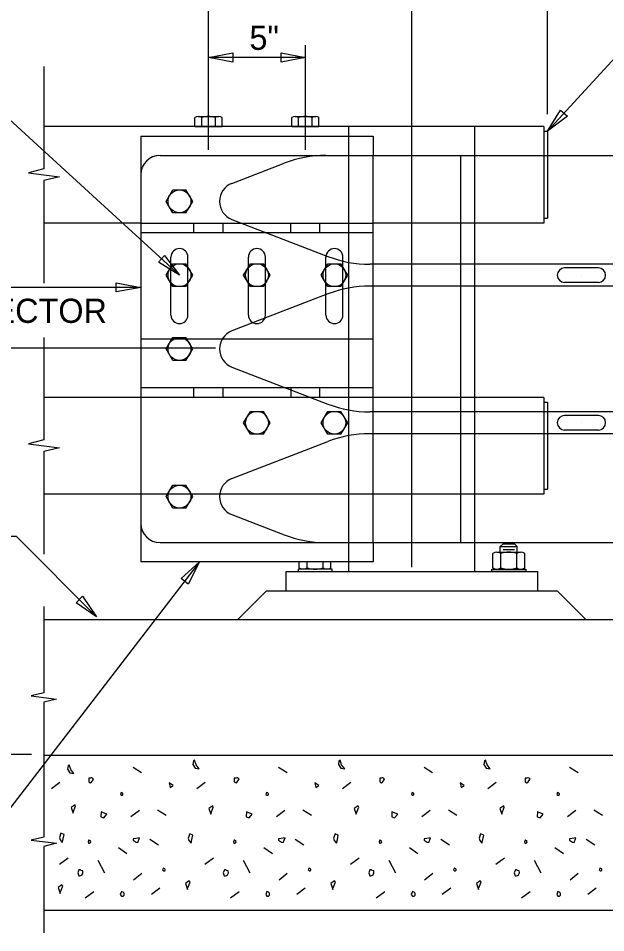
# Model space of a CAD drawing. Extents: x 0 to 22.7, y 0 to 15.7.
# Drawn here: x 17.22 to 19.747, y 9.623 to 13.56 of the extents above; entities that cross this region are included whole.
import ezdxf

# ---------------------------------------------------------------- set-up
doc = ezdxf.new("R2010")
doc.units = 0
for name, color, linetype in [('BRDG_ANNO_General-Notes', 7, 'Continuous'), ('BRDG_BASE_Active-Point', 7, 'Continuous'), ('BRDG_BASE_Dtlctrln', 7, 'Continuous'), ('BRDG_BASE_Hidden-Line', 7, 'Continuous'), ('BRDG_BASE_Obj-Line', 7, 'Continuous'), ('BRDG_BASE_Pattern', 7, 'Continuous'), ('BRDG_BASE_Rebar', 7, 'Continuous'), ('Default', 7, 'Continuous')]:
    doc.layers.add(name, color=color, linetype=linetype)

# ---------------------------------------------------------------- blocks, each defined once
blk = doc.blocks.new('TERM')
at = {"layer": 'Default'}
for p, q in [((-1.6, -0.267), (-1.6, 0.267)), ((-1.6, 0.267), (0, 0)), ((0, 0), (-1.6, -0.267))]:
    blk.add_line(p, q, dxfattribs=at)

msp = doc.modelspace()

# ---------------------------------------------------------------- linework, layer by layer
at = {"layer": 'BRDG_ANNO_General-Notes'}
for p, q in [((19.4969, 13.1468), (19.4969, 13.7448)), ((19.4967, 13.0735), (19.8494, 13.459)), ((18.4552, 13.3912), (18.0385, 13.3912)), ((17.9134, 12.4537), (17.0883, 13.2089)), ((17.7467, 12.4012), (15.937, 12.4012)), ((17.9997, 11.2193), (17.107, 10.0594)), ((17.2776, 10.3896), (15.6191, 10.3896))]:
    msp.add_line(p, q, dxfattribs=at)
msp.add_lwpolyline([(17.5565, 10.9831), (17.212, 11.3293), (16.0973, 11.3293)], dxfattribs=at)
at = {"layer": 'BRDG_BASE_Active-Point'}
for p, q in [((19.6426, 12.4537), (19.6426, 12.4537)), ((19.6426, 11.8183), (19.6426, 11.8183))]:
    msp.add_line(p, q, dxfattribs=at)
at = {"layer": 'BRDG_BASE_Dtlctrln'}
for p, q in [((18.9135, 11.1964), (18.9135, 14.0622)), ((18.0385, 12.9927), (18.0385, 13.7448)), ((18.4552, 12.9927), (18.4552, 13.4437)), ((18.0683, 12.1396), (15.6191, 12.1396))]:
    msp.add_line(p, q, dxfattribs=at)
at = {"layer": 'BRDG_BASE_Hidden-Line'}
for p, q in [((18.6426, 11.2193), (18.6426, 13.0943)), ((19.1842, 11.3027), (19.1842, 13.0943)), ((18.7467, 11.3027), (18.7467, 12.9693)), ((19.4811, 12.9693), (19.4811, 12.6777)), ((19.4967, 12.9693), (19.4967, 12.6985)), ((17.7467, 12.6777), (18.7467, 12.6777)), ((17.9759, 12.636), (17.9759, 12.6777)), ((18.1009, 12.636), (18.1009, 12.6777)), ((18.3926, 12.636), (18.3926, 12.6777)), ((18.5176, 12.636), (18.5176, 12.6777)), ((19.4811, 12.6777), (18.7467, 12.6777)), ((19.4811, 12.6985), (19.4967, 12.6985)), ((18.7467, 12.636), (17.7467, 12.636)), ((17.8769, 12.2818), (17.8769, 12.5318)), ((17.9498, 12.2818), (17.9498, 12.5318)), ((18.2103, 12.2818), (18.2103, 12.5318)), ((18.2832, 12.2818), (18.2832, 12.5318)), ((18.5436, 12.2818), (18.5436, 12.5318)), ((18.6165, 12.2818), (18.6165, 12.5318)), ((18.7467, 12.1777), (17.7467, 12.1777)), ((18.7467, 11.9693), (17.7467, 11.9693)), ((17.9759, 11.9277), (17.9759, 11.9693)), ((18.1009, 11.9277), (18.1009, 11.9693)), ((18.3926, 11.9693), (18.3926, 11.9277)), ((18.5176, 11.9277), (18.5176, 11.9693)), ((18.7467, 11.9277), (17.7467, 11.9277)), ((19.4811, 11.9277), (18.7467, 11.9277)), ((19.4811, 11.9277), (19.4811, 11.511)), ((19.4811, 11.9068), (19.4967, 11.9068)), ((19.4967, 11.9068), (19.4967, 11.5318)), ((19.4811, 11.511), (17.7467, 11.511)), ((19.4811, 11.5318), (19.4967, 11.5318))]:
    msp.add_line(p, q, dxfattribs=at)
for centre, start, end in [((17.9134, 12.5318), 0, 180), ((18.2467, 12.5318), 0, 180), ((18.5801, 12.5318), 0, 180), ((17.9134, 12.2818), 180, 0), ((18.2467, 12.2818), 180, 0), ((18.5801, 12.2818), 180, 0)]:
    msp.add_arc(centre, 0.0365, start, end, dxfattribs=at)
at = {"layer": 'BRDG_BASE_Obj-Line'}
for p, q in [((17.9798, 13.0943), (17.9798, 13.1327)), ((17.9941, 13.1372), (18.0384, 13.1372)), ((18.0091, 13.0943), (18.0091, 13.1327)), ((18.0384, 13.1372), (18.0827, 13.1372)), ((18.0677, 13.0943), (18.0677, 13.1327)), ((18.097, 13.0943), (18.097, 13.1327)), ((18.3965, 13.0943), (18.3965, 13.1327)), ((18.4108, 13.1372), (18.4551, 13.1372)), ((18.4258, 13.0943), (18.4258, 13.1327)), ((18.4551, 13.1372), (18.4994, 13.1372)), ((18.4844, 13.0943), (18.4844, 13.1327)), ((18.5136, 13.0943), (18.5136, 13.1327)), ((19.4811, 13.0943), (17.3301, 13.0943)), ((17.9798, 13.0943), (18.0384, 13.0943)), ((18.0384, 13.0943), (18.097, 13.0943)), ((18.3965, 13.0943), (18.4551, 13.0943)), ((18.4551, 13.0943), (18.5136, 13.0943)), ((19.4811, 13.0943), (19.4811, 12.9693)), ((19.4811, 13.0735), (19.4967, 13.0735)), ((19.4967, 13.0735), (19.4967, 12.9693)), ((17.7467, 13.0527), (17.7467, 11.2193)), ((17.7467, 13.0527), (18.7467, 13.0527)), ((18.7467, 13.0527), (18.7467, 12.9693)), ((17.8301, 12.9693), (19.1217, 12.9693)), ((19.1217, 12.9693), (20.8281, 12.9693)), ((19.1217, 12.9693), (19.1217, 11.3027)), ((18.139, 12.8491), (18.3633, 12.9358)), ((17.7467, 12.886), (17.7467, 11.386)), ((17.856, 12.7714), (17.8855, 12.8206)), ((17.8855, 12.8206), (17.9413, 12.8206)), ((17.9708, 12.7714), (17.9413, 12.8206)), ((17.8855, 12.7222), (17.856, 12.7714)), ((17.9413, 12.7222), (17.9708, 12.7714)), ((17.9413, 12.7222), (17.8855, 12.7222)), ((17.7467, 12.6777), (17.3301, 12.6777)), ((18.139, 12.6936), (18.5521, 12.5341)), ((17.856, 12.4537), (17.8855, 12.5029)), ((17.8855, 12.5029), (17.9413, 12.5029)), ((17.9708, 12.4537), (17.9413, 12.5029)), ((18.1893, 12.4537), (18.2189, 12.5029)), ((18.2189, 12.5029), (18.2746, 12.5029)), ((18.3042, 12.4537), (18.2746, 12.5029)), ((18.5227, 12.4537), (18.5522, 12.5029)), ((18.5522, 12.5029), (18.608, 12.5029)), ((18.6375, 12.4537), (18.608, 12.5029)), ((19.1217, 12.5006), (18.7322, 12.5006)), ((20.8281, 12.5006), (19.1217, 12.5006)), ((17.8855, 12.4045), (17.856, 12.4537)), ((17.9413, 12.4045), (17.9708, 12.4537)), ((18.2189, 12.4045), (18.1893, 12.4537)), ((18.2746, 12.4045), (18.3042, 12.4537)), ((18.5522, 12.4045), (18.5227, 12.4537)), ((18.608, 12.4045), (18.6375, 12.4537)), ((17.9413, 12.4045), (17.8855, 12.4045)), ((18.2746, 12.4045), (18.2189, 12.4045)), ((18.608, 12.4045), (18.5522, 12.4045)), ((19.1217, 12.4068), (18.7322, 12.4068)), ((20.8281, 12.4068), (19.1217, 12.4068)), ((18.5522, 12.3733), (18.139, 12.2137)), ((17.856, 12.136), (17.8855, 12.1852)), ((17.8855, 12.1852), (17.9413, 12.1852)), ((17.9708, 12.136), (17.9413, 12.1852)), ((17.8855, 12.0868), (17.856, 12.136)), ((17.9413, 12.0868), (17.9708, 12.136)), ((17.9413, 12.0868), (17.8855, 12.0868)), ((18.139, 12.0583), (18.5521, 11.8987)), ((17.7467, 11.9277), (17.3301, 11.9277)), ((18.1893, 11.8183), (18.2189, 11.8674)), ((18.2189, 11.8674), (18.2746, 11.8674)), ((18.3042, 11.8183), (18.2746, 11.8674)), ((18.5227, 11.8183), (18.5522, 11.8674)), ((18.5522, 11.8674), (18.608, 11.8674)), ((18.6375, 11.8183), (18.608, 11.8674)), ((19.1217, 11.8652), (18.7323, 11.8652)), ((20.8281, 11.8652), (19.1217, 11.8652)), ((18.2189, 11.7691), (18.1893, 11.8183)), ((18.2746, 11.7691), (18.3042, 11.8183)), ((18.5522, 11.7691), (18.5227, 11.8183)), ((18.608, 11.7691), (18.6375, 11.8183)), ((19.1217, 11.7714), (18.7322, 11.7714)), ((20.8281, 11.7714), (19.1217, 11.7714)), ((18.139, 11.5783), (18.5521, 11.7379)), ((18.2746, 11.7691), (18.2189, 11.7691)), ((18.608, 11.7691), (18.5522, 11.7691)), ((17.856, 11.5006), (17.8855, 11.5497)), ((17.8855, 11.5497), (17.9413, 11.5497)), ((17.9708, 11.5006), (17.9413, 11.5497)), ((17.7467, 11.511), (17.3301, 11.511)), ((17.8855, 11.4514), (17.856, 11.5006)), ((17.9413, 11.4514), (17.9708, 11.5006)), ((17.9413, 11.4514), (17.8855, 11.4514)), ((18.139, 11.4229), (18.3633, 11.3362)), ((17.8301, 11.3027), (19.1217, 11.3027)), ((18.7467, 11.3027), (18.7467, 11.2193)), ((19.1217, 11.3027), (20.8281, 11.3027)), ((19.1842, 11.1777), (19.1842, 11.3027)), ((19.2792, 11.261), (19.3301, 11.261)), ((19.2936, 11.2853), (19.3058, 11.2974)), ((19.2936, 11.261), (19.2936, 11.2853)), ((19.2936, 11.2853), (19.3665, 11.2853)), ((19.3058, 11.2974), (19.3544, 11.2974)), ((19.3058, 11.2731), (19.3544, 11.2731)), ((19.3301, 11.261), (19.3809, 11.261)), ((19.3544, 11.2974), (19.3665, 11.2853)), ((19.3665, 11.261), (19.3665, 11.2853)), ((19.2617, 11.1935), (19.2617, 11.2556)), ((19.2959, 11.1935), (19.2959, 11.2556)), ((19.3642, 11.1935), (19.3642, 11.2556)), ((19.3984, 11.1935), (19.3984, 11.2556)), ((18.7467, 11.2193), (17.7467, 11.2193)), ((18.4284, 11.1935), (18.4284, 11.2193)), ((18.4967, 11.1881), (18.4459, 11.1881)), ((18.4626, 11.1935), (18.4626, 11.2193)), ((18.5476, 11.1881), (18.4967, 11.1881)), ((18.5309, 11.1935), (18.5309, 11.2193)), ((18.5651, 11.1935), (18.5651, 11.2193)), ((18.6426, 11.1777), (18.6426, 11.2193)), ((19.2792, 11.1881), (19.3301, 11.1881)), ((19.3301, 11.1881), (19.3809, 11.1881)), ((18.3717, 11.1777), (19.4551, 11.1777)), ((18.3717, 11.0943), (18.3717, 11.1777)), ((19.4551, 11.0943), (19.4551, 11.1777)), ((18.1634, 10.9693), (18.2884, 11.0943)), ((18.2884, 11.0943), (19.5384, 11.0943)), ((19.6634, 10.9693), (19.5384, 11.0943)), ((19.9759, 10.9693), (17.3301, 10.9693)), ((19.9759, 10.386), (17.3301, 10.386)), ((19.9759, 9.7193), (17.3301, 9.7193))]:
    msp.add_line(p, q, dxfattribs=at)
for points in [[(17.3301, 13.3527), (17.3301, 12.911), (17.2634, 12.8943), (17.3301, 12.886), (17.3967, 12.8777), (17.3301, 12.861), (17.3301, 12.4193)], [(17.3301, 12.186), (17.3301, 11.7443), (17.2634, 11.7277), (17.3301, 11.7193), (17.3967, 11.711), (17.3301, 11.6943), (17.3301, 11.2527)], [(17.3301, 11.027), (17.3301, 10.6557), (17.276, 10.6422), (17.3841, 10.6288), (17.3301, 10.6153), (17.3301, 10.325), (17.3301, 10.0347), (17.276, 10.0213), (17.3841, 10.0078), (17.3301, 9.9942), (17.3301, 9.623)]]:
    msp.add_lwpolyline(points, dxfattribs=at)
for points in [[(18.5696, 11.1777), (18.5696, 11.1881), (18.4238, 11.1881), (18.4238, 11.1777)], [(19.2571, 11.1777), (19.2571, 11.1881), (19.403, 11.1881), (19.403, 11.1777)]]:
    msp.add_lwpolyline(points, close=True, dxfattribs=at)
for centre in [(17.9134, 12.7714), (17.9134, 12.4537), (18.2467, 12.4537), (18.5801, 12.4537), (17.9134, 12.136), (18.2467, 11.8183), (18.5801, 11.8183), (17.9134, 11.5006)]:
    msp.add_circle(centre, 0.0492, dxfattribs=at)
for centre, radius, start, end in [((17.9945, 13.1119), 0.0254, 54.7697, 125.2303), ((18.0384, 13.0426), 0.0946, 71.9685, 108.0316), ((18.0823, 13.1119), 0.0254, 54.7697, 125.2303), ((18.4111, 13.1119), 0.0254, 54.7697, 125.2303), ((18.4551, 13.0426), 0.0946, 71.9685, 108.0316), ((18.499, 13.1119), 0.0254, 54.7697, 125.2303), ((17.8301, 12.886), 0.0833, 90, 180), ((18.5434, 12.4693), 0.5, 90, 111.1075), ((18.169, 12.7714), 0.0833, 111.116, 248.8803), ((18.7322, 13.0006), 0.5, 248.8932, 270), ((18.7322, 11.9068), 0.5, 90, 111.0988), ((18.169, 12.136), 0.0833, 111.12, 248.8837), ((18.7323, 12.3651), 0.5, 248.8804, 270), ((18.7322, 11.2714), 0.5, 90, 111.1068), ((18.169, 11.5006), 0.0833, 111.1197, 248.884), ((17.8301, 11.386), 0.0833, 180, 270), ((18.5434, 11.8026), 0.5, 248.8925, 270), ((19.2788, 11.2313), 0.0296, 54.7697, 125.2303), ((19.3301, 11.1506), 0.1104, 71.9685, 108.0316), ((19.3813, 11.2313), 0.0296, 54.7697, 125.2303), ((18.4455, 11.2177), 0.0296, 234.7697, 305.2303), ((18.4967, 11.2985), 0.1104, 251.9685, 288.0316), ((18.548, 11.2177), 0.0296, 234.7697, 305.2303), ((19.2788, 11.2177), 0.0296, 234.7697, 305.2303), ((19.3301, 11.2985), 0.1104, 251.9684, 288.0315), ((19.3813, 11.2177), 0.0296, 234.7697, 305.2303)]:
    msp.add_arc(centre, radius, start, end, dxfattribs=at)
at = {"layer": 'BRDG_BASE_Pattern'}
for p, q in [((17.7137, 10.3353), (17.7506, 10.3123)), ((18.3395, 10.3353), (18.3765, 10.3123)), ((18.9654, 10.3353), (19.0023, 10.3123)), ((19.5912, 10.3353), (19.6281, 10.3123)), ((17.3987, 10.2697), (17.3627, 10.2427)), ((18.0246, 10.2697), (17.9885, 10.2427)), ((18.6504, 10.2697), (18.6143, 10.2427)), ((19.2762, 10.2697), (19.2402, 10.2427)), ((17.7408, 10.1491), (17.7047, 10.1221)), ((17.8187, 10.1516), (17.8556, 10.1294)), ((18.3666, 10.1491), (18.3305, 10.1221)), ((18.4445, 10.1516), (18.4815, 10.1294)), ((18.9924, 10.1491), (18.9564, 10.1221)), ((19.0704, 10.1516), (19.1072, 10.1294)), ((19.6182, 10.1491), (19.5821, 10.1221)), ((19.6961, 10.1516), (19.7331, 10.1294)), ((17.7859, 10.0253), (17.8228, 10.0015)), ((18.4117, 10.0253), (18.4486, 10.0015)), ((19.0376, 10.0253), (19.0744, 10.0015)), ((19.6634, 10.0253), (19.7003, 10.0015)), ((17.6506, 9.9892), (17.6875, 9.9646)), ((18.2764, 9.9892), (18.3133, 9.9646)), ((18.9022, 9.9892), (18.9391, 9.9646)), ((19.528, 9.9892), (19.5649, 9.9646)), ((17.434, 9.9441), (17.3971, 9.917)), ((17.562, 9.9351), (17.5907, 9.8809)), ((18.0598, 9.9441), (18.0229, 9.917)), ((18.1878, 9.9351), (18.2165, 9.8809)), ((18.6857, 9.9441), (18.6487, 9.917)), ((18.8136, 9.9351), (18.8423, 9.8809)), ((19.3115, 9.9441), (19.2746, 9.917)), ((19.4394, 9.9351), (19.4681, 9.8809)), ((17.7515, 9.8777), (17.7162, 9.8489)), ((18.3773, 9.8777), (18.342, 9.8489)), ((19.0031, 9.8777), (18.9678, 9.8489)), ((19.6289, 9.8777), (19.5936, 9.8489)), ((17.8285, 9.8145), (17.7924, 9.7874)), ((18.4544, 9.8145), (18.4183, 9.7874)), ((19.0802, 9.8145), (19.0441, 9.7874)), ((19.706, 9.8145), (19.6699, 9.7874)), ((17.5447, 9.7989), (17.5079, 9.7718)), ((18.1706, 9.7989), (18.1336, 9.7718)), ((18.7964, 9.7989), (18.7595, 9.7718)), ((19.4222, 9.7989), (19.3853, 9.7718))]:
    msp.add_line(p, q, dxfattribs=at)
for points in [[(17.9737, 10.3624), (17.9712, 10.3476), (17.9811, 10.3312), (17.9983, 10.3287), (17.9852, 10.346), (17.9786, 10.3657)], [(18.5995, 10.3624), (18.5971, 10.3476), (18.6069, 10.3312), (18.6242, 10.3287), (18.611, 10.346), (18.6045, 10.3657)], [(19.2254, 10.3624), (19.2229, 10.3476), (19.2328, 10.3312), (19.25, 10.3287), (19.2369, 10.346), (19.2303, 10.3657)], [(17.4342, 10.3421), (17.4317, 10.3273), (17.4416, 10.3109), (17.4587, 10.3084), (17.4456, 10.3257), (17.4391, 10.3454)], [(17.5234, 10.2885), (17.5234, 10.2721), (17.5308, 10.2681), (17.5341, 10.2697), (17.539, 10.2762), (17.544, 10.2845), (17.5398, 10.2885), (17.5366, 10.2902), (17.5341, 10.2902), (17.53, 10.2885)], [(18.1493, 10.2885), (18.1493, 10.2721), (18.1566, 10.2681), (18.1599, 10.2697), (18.1648, 10.2762), (18.1697, 10.2845), (18.1657, 10.2885), (18.1624, 10.2902), (18.1599, 10.2902), (18.1558, 10.2885)], [(18.7751, 10.2885), (18.7751, 10.2721), (18.7824, 10.2681), (18.7857, 10.2697), (18.7907, 10.2762), (18.7956, 10.2845), (18.7915, 10.2885), (18.7882, 10.2902), (18.7857, 10.2902), (18.7816, 10.2885)], [(19.4009, 10.2885), (19.4009, 10.2721), (19.4083, 10.2681), (19.4116, 10.2697), (19.4165, 10.2762), (19.4214, 10.2845), (19.4173, 10.2885), (19.414, 10.2902), (19.4116, 10.2902), (19.4074, 10.2885)], [(17.8696, 10.2681), (17.8736, 10.2484), (17.8868, 10.2574)], [(18.4954, 10.2681), (18.4995, 10.2484), (18.5126, 10.2574)], [(19.1212, 10.2681), (19.1253, 10.2484), (19.1384, 10.2574)], [(17.662, 10.227), (17.6596, 10.218), (17.6629, 10.2147), (17.6678, 10.2147), (17.6703, 10.2172), (17.6703, 10.2205), (17.6694, 10.223), (17.667, 10.2246)], [(18.2879, 10.227), (18.2854, 10.218), (18.2887, 10.2147), (18.2936, 10.2147), (18.2961, 10.2172), (18.2961, 10.2205), (18.2953, 10.223), (18.2928, 10.2246)], [(18.9137, 10.227), (18.9112, 10.218), (18.9145, 10.2147), (18.9194, 10.2147), (18.9219, 10.2172), (18.9219, 10.2205), (18.9211, 10.223), (18.9186, 10.2246)], [(19.5395, 10.227), (19.537, 10.218), (19.5403, 10.2147), (19.5453, 10.2147), (19.5477, 10.2172), (19.5477, 10.2205), (19.5469, 10.223), (19.5444, 10.2246)], [(17.4471, 10.1622), (17.4562, 10.1377), (17.4562, 10.1401), (17.4668, 10.1688), (17.4644, 10.1738)], [(18.0393, 10.1573), (18.0484, 10.1327), (18.0484, 10.1352), (18.059, 10.1639), (18.0566, 10.1688)], [(18.6652, 10.1573), (18.6742, 10.1327), (18.6742, 10.1352), (18.6848, 10.1639), (18.6824, 10.1688)], [(19.291, 10.1573), (19.3, 10.1327), (19.3, 10.1352), (19.3107, 10.1639), (19.3082, 10.1688)], [(17.5759, 10.1434), (17.5751, 10.1212), (17.5874, 10.118), (17.6005, 10.1327)], [(18.2018, 10.1434), (18.2009, 10.1212), (18.2132, 10.118), (18.2264, 10.1327)], [(18.8276, 10.1434), (18.8268, 10.1212), (18.8391, 10.118), (18.8522, 10.1327)], [(19.4534, 10.1434), (19.4526, 10.1212), (19.4649, 10.118), (19.478, 10.1327)], [(17.4037, 10.0509), (17.3972, 10.0329), (17.3996, 10.023), (17.4095, 10.0107), (17.4136, 10.0271), (17.4169, 10.046)], [(17.9573, 10.0482), (17.9508, 10.0302), (17.9532, 10.0204), (17.9631, 10.0081), (17.9672, 10.0245), (17.9705, 10.0433)], [(18.5831, 10.0482), (18.5766, 10.0302), (18.5791, 10.0204), (18.5889, 10.0081), (18.593, 10.0245), (18.5962, 10.0433)], [(19.209, 10.0482), (19.2024, 10.0302), (19.2048, 10.0204), (19.2147, 10.0081), (19.2188, 10.0245), (19.2221, 10.0433)], [(17.5202, 10.0138), (17.5218, 10.0081), (17.5243, 10.0081), (17.5267, 10.0081), (17.5292, 10.0105), (17.5316, 10.0138), (17.53, 10.0187), (17.5267, 10.0187), (17.5251, 10.0212), (17.5226, 10.0212)], [(17.7252, 10.0285), (17.7137, 10.0278), (17.7137, 10.0212), (17.7268, 10.0121), (17.7342, 10.0114), (17.7416, 10.0318)], [(18.146, 10.0138), (18.1476, 10.0081), (18.1501, 10.0081), (18.1526, 10.0081), (18.155, 10.0105), (18.1574, 10.0138), (18.1558, 10.0187), (18.1526, 10.0187), (18.1509, 10.0212), (18.1484, 10.0212)], [(18.351, 10.0285), (18.3395, 10.0278), (18.3395, 10.0212), (18.3527, 10.0121), (18.3601, 10.0114), (18.3674, 10.0318)], [(18.7718, 10.0138), (18.7734, 10.0081), (18.7759, 10.0081), (18.7783, 10.0081), (18.7808, 10.0105), (18.7833, 10.0138), (18.7816, 10.0187), (18.7783, 10.0187), (18.7767, 10.0212), (18.7743, 10.0212)], [(18.9768, 10.0285), (18.9654, 10.0278), (18.9654, 10.0212), (18.9785, 10.0121), (18.9859, 10.0114), (18.9932, 10.0318)], [(19.3976, 10.0138), (19.3993, 10.0081), (19.4017, 10.0081), (19.4042, 10.0081), (19.4066, 10.0105), (19.4091, 10.0138), (19.4074, 10.0187), (19.4042, 10.0187), (19.4026, 10.0212), (19.4001, 10.0212)], [(19.6027, 10.0285), (19.5912, 10.0278), (19.5912, 10.0212), (19.6043, 10.0121), (19.6117, 10.0114), (19.6191, 10.0318)], [(17.4759, 9.8809), (17.4799, 9.8678), (17.4849, 9.8678), (17.4898, 9.8686), (17.4947, 9.8727), (17.498, 9.8809), (17.4972, 9.8899), (17.4898, 9.8908), (17.4873, 9.8932), (17.4808, 9.8932)], [(17.8449, 9.9022), (17.8408, 9.8932), (17.8449, 9.8899), (17.8499, 9.8899), (17.8523, 9.8924), (17.8523, 9.8957), (17.8507, 9.8981), (17.8482, 9.8998)], [(18.1017, 9.8809), (18.1058, 9.8678), (18.1107, 9.8678), (18.1156, 9.8686), (18.1205, 9.8727), (18.1238, 9.8809), (18.123, 9.8899), (18.1156, 9.8908), (18.1132, 9.8932), (18.1066, 9.8932)], [(18.4708, 9.9022), (18.4667, 9.8932), (18.4708, 9.8899), (18.4757, 9.8899), (18.4782, 9.8924), (18.4782, 9.8957), (18.4765, 9.8981), (18.4741, 9.8998)], [(18.7275, 9.8809), (18.7316, 9.8678), (18.7365, 9.8678), (18.7415, 9.8686), (18.7464, 9.8727), (18.7496, 9.8809), (18.7488, 9.8899), (18.7415, 9.8908), (18.739, 9.8932), (18.7324, 9.8932)], [(19.0966, 9.9022), (19.0925, 9.8932), (19.0966, 9.8899), (19.1015, 9.8899), (19.104, 9.8924), (19.104, 9.8957), (19.1023, 9.8981), (19.0999, 9.8998)], [(19.3533, 9.8809), (19.3574, 9.8678), (19.3623, 9.8678), (19.3672, 9.8686), (19.3722, 9.8727), (19.3755, 9.8809), (19.3746, 9.8899), (19.3672, 9.8908), (19.3648, 9.8932), (19.3582, 9.8932)], [(19.7224, 9.9022), (19.7183, 9.8932), (19.7224, 9.8899), (19.7273, 9.8899), (19.7298, 9.8924), (19.7298, 9.8957), (19.7282, 9.8981), (19.7257, 9.8998)], [(17.9393, 9.835), (17.9475, 9.8087), (17.9475, 9.8129), (17.959, 9.8399), (17.9548, 9.8456)], [(18.5651, 9.835), (18.5733, 9.8087), (18.5733, 9.8129), (18.5848, 9.8399), (18.5807, 9.8456)], [(19.1909, 9.835), (19.1991, 9.8087), (19.1991, 9.8129), (19.2106, 9.8399), (19.2065, 9.8456)], [(17.3918, 9.8181), (17.4, 9.7919), (17.4, 9.796), (17.4115, 9.823), (17.4074, 9.8288)], [(17.6637, 9.7997), (17.6587, 9.7874), (17.6637, 9.7808), (17.6711, 9.7808), (17.6752, 9.7849), (17.6752, 9.7915), (17.6735, 9.794), (17.6711, 9.7972)], [(18.2895, 9.7997), (18.2846, 9.7874), (18.2895, 9.7808), (18.2969, 9.7808), (18.301, 9.7849), (18.301, 9.7915), (18.2994, 9.794), (18.2969, 9.7972)], [(18.9153, 9.7997), (18.9104, 9.7874), (18.9153, 9.7808), (18.9227, 9.7808), (18.9268, 9.7849), (18.9268, 9.7915), (18.9252, 9.794), (18.9227, 9.7972)], [(19.5411, 9.7997), (19.5362, 9.7874), (19.5411, 9.7808), (19.5485, 9.7808), (19.5527, 9.7849), (19.5527, 9.7915), (19.551, 9.794), (19.5485, 9.7972)]]:
    msp.add_lwpolyline(points, close=True, dxfattribs=at)
at = {"layer": 'BRDG_BASE_Rebar'}
for p, q in [((19.7155, 12.4849), (19.5696, 12.4849)), ((19.7155, 12.4224), (19.5696, 12.4224)), ((19.7155, 11.8495), (19.5696, 11.8495)), ((19.7155, 11.787), (19.5696, 11.787))]:
    msp.add_line(p, q, dxfattribs=at)
for centre, start, end in [((19.5697, 12.4537), 90, 270), ((19.7155, 12.4537), 270, 90), ((19.5697, 11.8183), 90, 270), ((19.7155, 11.8183), 270, 90)]:
    msp.add_arc(centre, 0.0312, start, end, dxfattribs=at)

# ---------------------------------------------------------------- block references
at = {"layer": 'BRDG_ANNO_General-Notes'}
for p, xscale, yscale, rotation in [((18.0386, 13.3912), 0.06561679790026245, 0.07381889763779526, 180), ((19.4967, 13.0735), 0.06561679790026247, 0.07381889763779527, -132.4551956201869), ((17.9134, 12.4537), 0.06561679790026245, 0.07381889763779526, -42.466441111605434), ((17.9997, 11.2193), 0.06561679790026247, 0.07381889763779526, 52.415074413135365), ((17.5565, 10.9831), 0.06561679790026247, 0.07381889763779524, -45.13609423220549)]:
    msp.add_blockref('TERM', p, dxfattribs=dict(at, xscale=xscale, yscale=yscale, rotation=rotation))
at = {"layer": 'BRDG_ANNO_General-Notes', "xscale": 0.06561679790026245, "yscale": 0.07381889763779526}
for p in [(18.4552, 13.3912), (17.7467, 12.4012)]:
    msp.add_blockref('TERM', p, dxfattribs=at)

# ---------------------------------------------------------------- texts
at = {"layer": 'BRDG_ANNO_General-Notes'}
for s, height, p in [('5"', 0.10417, (18.2143, 13.4238)), ('TERMINAL CONNECTOR', 0.104167, (15.9606, 12.2484))]:
    msp.add_text(s, height=height, dxfattribs=at).set_placement(p)

doc.saveas('drawing.dxf')
